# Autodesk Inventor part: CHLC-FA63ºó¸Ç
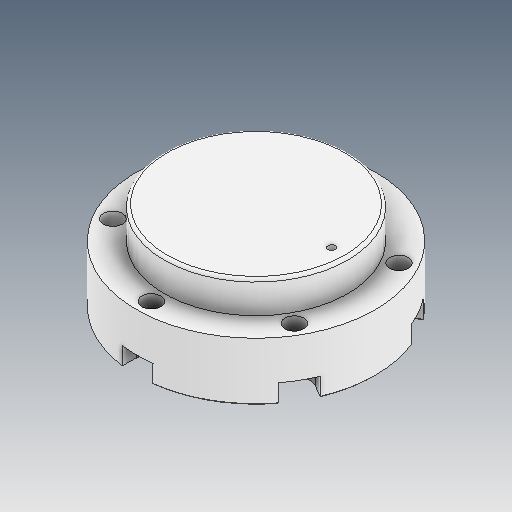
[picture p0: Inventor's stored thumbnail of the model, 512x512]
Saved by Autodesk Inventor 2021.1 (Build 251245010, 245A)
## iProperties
Created: 2021-05
Part Number: CHLC-FA63ºó¸Ç
Material: Ogólny
Document SubType Name: Modeling
Designer: user
Density: 1 g/cm^3
Appearance: Domyślna
Author: user
Revision Number: ÈÎºÎ
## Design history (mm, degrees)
feature "ÊäÈë3"
node "Bryła1"
